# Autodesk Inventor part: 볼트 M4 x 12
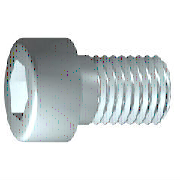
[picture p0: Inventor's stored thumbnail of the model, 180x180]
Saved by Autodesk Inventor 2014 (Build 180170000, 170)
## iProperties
IsCustomPart: 0
Created: 2012-02
Part Number: 볼트 M4 x 12
Material: 스테인리스강
Description: 6각 소켓 머리 캡 나사
Document SubType Name: Modeling
Standard: ISO 4762
Designer: mduedu
Standard Revision: Fourth edition 2004-03-01
Standards Organization: ISO
Language: ko-KR
Size Designation: M4 x 12
Categories: <MemberInstance><Categories><Category DisplayName="조임쇠" InternalName="e4da775c-781d-43d5-af7c-5136215cf5a6" Mnemonic="FSTN"><Category DisplayName="볼트" InternalN
Density: 8.08 g/cm^3
Mass: 2.29719 g
Surface Area: 3.30853 cm^2
Volume: 0.284306 cm^3
Appearance: 반광택
Author: mduedu
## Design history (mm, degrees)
sketch "스케치1"
  geometry: L1 (-1, 0)-(12, 0); L2 (12, 0)-(12, 2); L3 (12, 2)-(1.75, 2); L4 (1.75, 2)-(1.32, 2); L5 (1.32, 2)-(0, 2); L6 (0, 2)-(0, 3.5); L7 (0, 3.5)-(-4, 3.5); L8 (-4, 3.5)-(-4, 1.732); L9 (-4, 1.732)-(-2, 1.732); L10 (-2, 1.732)-(-1, 0); L11 (-7.2, 0)-(15.2, 0) reference; L12 (0, -0.7)-(0, 4.2) reference; L13 (1.75, 2)-(0, 2)
  constraints: 22 end point, 6 parallel, 2 collinear, 2 perpendicular, 1 horizontal, 1 point on line
  dimensions: "d1" = 10.25 distance from line of L3.end L2 (= GEL); "d2" = 0.42952 distance of L4.end L3.end (computed from GAL); "d3" = 4 distance between parallel lines of L8 L6 (= KOH); "d4" = 2 distance of L8.end L9.end (= INTI); "d5" = 60 deg angle of L10 L1; "d6" = 4 diameter of L3 L1 (= GD); "d7" = 4 diameter of L5 L1 (= BDM); "d8" = 3.4641 diameter of L9 L1 (= 1.1547 x SW); "d9" = 7 diameter of L7 L1 (= KOD); "d26" = 12 distance between parallel lines of L12 L2 (= NLG)
revolve "본체" sketch "스케치1" stored, may be unused: angle "d10" = 90 deg
sketch "스케치2"
  geometry: L1 (0, -4.9)-(0, 4.9) reference; L2 (-4.9, 0)-(4.9, 0) reference; L3 (1.732, 0)-(0.866, -1.5); L4 (0.866, -1.5)-(-0.866, -1.5); L5 (-0.866, -1.5)-(-1.732, 0); L6 (-1.732, 0)-(-0.866, 1.5); L7 (-0.866, 1.5)-(0.866, 1.5); L8 (0.866, 1.5)-(1.732, 0); 2 further points
  constraints: 12 end point, 1 coincident, 1 horizontal alignment, 1 point on line, 12 other
extrude "슬롯" join sketch "스케치2" stored distance "d11" = 10; taper "d12" = 0 deg
workplane "Work Plane1"
fillet "Fillet2" dims "d30" = 0.1 (= R)
body "Solid1"
fillet "모깎기1" dims "d17" = 0.4 (= RR)
feature "스레드" dims "d13" = 10.25 (= GEL), "d14" = 0
chamfer "모따기1" distance "d15" = 0.42941 (= -0.5 x SPD + 0.5 x GD); stored, may be unused: second distance "d16" = 0.42941 (= GUL), angle "d27" = 45 deg
other parameters: "GD" = 4 [user parameter; used in 2 equation terms], "NLG" = 12 [user parameter; used in 1 equation term], "GEL" = 10.25 [user parameter; used in 2 equation terms], "KOD" = 7 [user parameter; used in 1 equation term], "KOH" = 4 [user parameter; used in 1 equation term], "INTI" = 2 [user parameter; used in 1 equation term], "GAL" = 0.42941 (= 0.61345 x PTC) [user parameter; used in 1 equation term], "GUL" = 0.42941 (= 0.61345 x PTC) [user parameter; used in 1 equation term], "BDM" = 4 (= NND) [user parameter; used in 1 equation term], "SW" = 3 [user parameter; used in 2 equation terms], "RR" = 0.4 [user parameter; used in 1 equation term], "SPD" = 3.14117 (= NND - 1.2269 x PTC) [user parameter; used in 1 equation term], "d19" = 0, "d28" = 0, "d29" = 0, "R" = 0.1 [user parameter; used in 1 equation term], "TOA" = 30 deg [user parameter], "GD1" = 3.14117 (= THREADDIA - 1.2269 x PTC) [user parameter], "THREADDIA" = 4 [user parameter; used in 1 equation term], "FAWI" = 45 deg [user parameter], "TPU" = 14.28571 (computed from PTC) [user parameter], "PTC" = 0.7 [user parameter; used in 5 equation terms], "NND" = 4 [user parameter; used in 2 equation terms], "E0" = 3.465 (= 1.155 x SW) [user parameter]
